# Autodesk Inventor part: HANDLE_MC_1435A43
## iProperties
Created: 2009-01
Part Number: HANDLE_MC_1435A43
Document SubType Name: Modeling
Designer: claivier
Norme de conversion: STEP AP214IS
Nom du fichier: HANDLE_MC_1435A43.STEP
Préprocesseur: SolidWorks 2008
Postprocesseur: Build: 344a, Release: 11 SP2 - Date: Fri 08/18/2006
Unités envoyées: INCHES
Incertitude: 1e-05
Author: claivier
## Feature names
1. Base1
